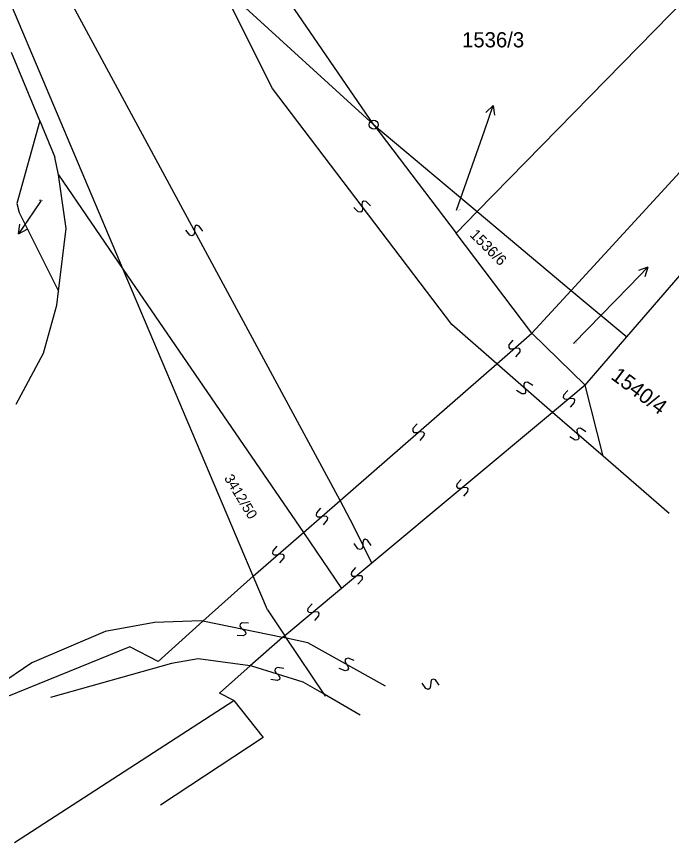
# Model space of a CAD drawing. Extents: x -601196 to -600262, y -1082523 to -1081922.
# Drawn here: x -600445.93 to -600409.27, y -1082422.91 to -1082376.65 of the extents above; entities that cross this region are included whole.
import ezdxf

# ---------------------------------------------------------------- set-up
doc = ezdxf.new("R2010")
doc.units = 0
doc.layers.add('Vrstva 47', color=7, linetype='Continuous')

msp = doc.modelspace()

# ---------------------------------------------------------------- linework, layer by layer
at = {"layer": 'Vrstva 47'}
for p, q in [((-600420.14, -1082387.57), (-600313.5, -1082278.63)), ((-600394.57, -1082369.86), (-600414.88, -1082391.99)), ((-600427.81, -1082403.75), (-600444.13, -1082373.53)), ((-600425.93, -1082382.71), (-600431.86, -1082374.05)), ((-600431.6, -1082380.69), (-600434.49, -1082374.9)), ((-600434.49, -1082374.9), (-600425.93, -1082382.71)), ((-600439.95, -1082390.82), (-600446.47, -1082375.4)), ((-600444.63, -1082382.49), (-600446.21, -1082378.67)), ((-600421.56, -1082393.91), (-600431.6, -1082380.69)), ((-600411.77, -1082394.6), (-600399.71, -1082380.62)), ((-600419.74, -1082383.05), (-600419.251, -1082381.631)), ((-600419.251, -1082381.631), (-600419.65, -1082382.023)), ((-600419.251, -1082381.631), (-600419.178, -1082382.185)), ((-600444.63, -1082382.49), (-600445.91, -1082387.13)), ((-600444.63, -1082382.49), (-600443.79, -1082384.53)), ((-600425.93, -1082382.71), (-600421.32, -1082388.78)), ((-600425.93, -1082382.71), (-600420.14, -1082387.57)), ((-600421.3, -1082387.5), (-600419.74, -1082383.05)), ((-600443.58, -1082385.51), (-600443.79, -1082384.53)), ((-600443.58, -1082385.51), (-600439.95, -1082390.82)), ((-600443.14, -1082388.53), (-600443.58, -1082385.51)), ((-600445.91, -1082387.13), (-600445.77, -1082387.63)), ((-600444.54, -1082386.96), (-600444.97, -1082387.59)), ((-600426.581, -1082387.05), (-600426.6, -1082387.19)), ((-600426.501, -1082386.989), (-600426.581, -1082387.05)), ((-600426.361, -1082387.008), (-600426.501, -1082386.989)), ((-600426.11, -1082387.257), (-600426.361, -1082387.008)), ((-600444.97, -1082387.59), (-600445.817, -1082388.827)), ((-600445.77, -1082387.63), (-600443.57, -1082392.04)), ((-600426.798, -1082387.591), (-600427.049, -1082387.342)), ((-600426.658, -1082387.61), (-600426.798, -1082387.591)), ((-600426.578, -1082387.55), (-600426.658, -1082387.61)), ((-600426.6, -1082387.19), (-600426.559, -1082387.409)), ((-600426.559, -1082387.409), (-600426.578, -1082387.55)), ((-600421.32, -1082388.78), (-600420.14, -1082387.57)), ((-600420.14, -1082387.57), (-600414.88, -1082391.99)), ((-600445.817, -1082388.827), (-600445.741, -1082388.274)), ((-600445.817, -1082388.827), (-600445.328, -1082388.556)), ((-600443.57, -1082392.04), (-600443.14, -1082388.53)), ((-600435.933, -1082388.392), (-600435.973, -1082388.528)), ((-600435.973, -1082388.528), (-600435.966, -1082388.751)), ((-600435.845, -1082388.345), (-600435.933, -1082388.392)), ((-600435.709, -1082388.385), (-600435.845, -1082388.345)), ((-600435.499, -1082388.669), (-600435.709, -1082388.385)), ((-600436.23, -1082388.894), (-600436.44, -1082388.61)), ((-600436.094, -1082388.934), (-600436.23, -1082388.894)), ((-600436.006, -1082388.887), (-600436.094, -1082388.934)), ((-600435.966, -1082388.751), (-600436.006, -1082388.887)), ((-600417.08, -1082394.38), (-600421.32, -1082388.78)), ((-600439.95, -1082390.82), (-600429.87, -1082405.55)), ((-600432.68, -1082408), (-600439.95, -1082390.82)), ((-600411.63, -1082391.77), (-600410.588, -1082390.691)), ((-600410.588, -1082390.691), (-600411.115, -1082390.877)), ((-600410.588, -1082390.691), (-600410.755, -1082391.224)), ((-600414.75, -1082394.96), (-600411.63, -1082391.77)), ((-600443.66, -1082392.81), (-600443.57, -1082392.04)), ((-600417.08, -1082394.38), (-600414.88, -1082391.99)), ((-600414.88, -1082391.99), (-600411.77, -1082394.6)), ((-600444.41, -1082395.51), (-600443.66, -1082392.81)), ((-600419.05, -1082396.1), (-600421.56, -1082393.91)), ((-600419.05, -1082396.1), (-600417.08, -1082394.38)), ((-600417.08, -1082394.38), (-600414.1, -1082397.3)), ((-600418.139, -1082394.774), (-600418.37, -1082395.042)), ((-600414.1, -1082397.3), (-600411.77, -1082394.6)), ((-600418.37, -1082395.042), (-600418.38, -1082395.183)), ((-600418.38, -1082395.183), (-600418.314, -1082395.258)), ((-600418.314, -1082395.258), (-600418.173, -1082395.268)), ((-600418.173, -1082395.268), (-600417.956, -1082395.211)), ((-600417.759, -1082395.437), (-600417.99, -1082395.705)), ((-600417.956, -1082395.211), (-600417.815, -1082395.221)), ((-600417.815, -1082395.221), (-600417.749, -1082395.296)), ((-600417.749, -1082395.296), (-600417.759, -1082395.437)), ((-600445.94, -1082398.37), (-600444.41, -1082395.51)), ((-600427.81, -1082403.75), (-600419.05, -1082396.1)), ((-600415.92, -1082398.82), (-600419.05, -1082396.1)), ((-600417.471, -1082397.14), (-600417.537, -1082397.215)), ((-600417.537, -1082397.215), (-600417.527, -1082397.356)), ((-600417.33, -1082397.13), (-600417.471, -1082397.14)), ((-600417.033, -1082397.322), (-600417.33, -1082397.13)), ((-600414.1, -1082397.3), (-600415.92, -1082398.82)), ((-600413.1, -1082401.27), (-600414.1, -1082397.3)), ((-600417.639, -1082397.789), (-600417.936, -1082397.597)), ((-600417.498, -1082397.779), (-600417.639, -1082397.789)), ((-600417.527, -1082397.356), (-600417.442, -1082397.563)), ((-600417.432, -1082397.704), (-600417.498, -1082397.779)), ((-600417.442, -1082397.563), (-600417.432, -1082397.704)), ((-600415.074, -1082397.592), (-600415.311, -1082397.855)), ((-600415.311, -1082397.855), (-600415.323, -1082397.996)), ((-600415.323, -1082397.996), (-600415.259, -1082398.073)), ((-600415.259, -1082398.073), (-600415.118, -1082398.085)), ((-600415.118, -1082398.085), (-600414.901, -1082398.034)), ((-600414.708, -1082398.264), (-600414.945, -1082398.527)), ((-600414.901, -1082398.034), (-600414.76, -1082398.046)), ((-600414.76, -1082398.046), (-600414.696, -1082398.123)), ((-600414.696, -1082398.123), (-600414.708, -1082398.264)), ((-600415.92, -1082398.82), (-600426.04, -1082407.27)), ((-600413.1, -1082401.27), (-600415.92, -1082398.82)), ((-600423.504, -1082399.459), (-600423.735, -1082399.727)), ((-600423.735, -1082399.727), (-600423.745, -1082399.868)), ((-600423.745, -1082399.868), (-600423.679, -1082399.943)), ((-600423.679, -1082399.943), (-600423.538, -1082399.953)), ((-600423.538, -1082399.953), (-600423.321, -1082399.896)), ((-600423.321, -1082399.896), (-600423.18, -1082399.906)), ((-600423.18, -1082399.906), (-600423.114, -1082399.981)), ((-600423.114, -1082399.981), (-600423.124, -1082400.122)), ((-600414.497, -1082399.725), (-600414.562, -1082399.8)), ((-600414.562, -1082399.8), (-600414.552, -1082399.941)), ((-600414.552, -1082399.941), (-600414.467, -1082400.148)), ((-600414.355, -1082399.715), (-600414.497, -1082399.725)), ((-600414.058, -1082399.907), (-600414.355, -1082399.715)), ((-600423.124, -1082400.122), (-600423.355, -1082400.39)), ((-600414.664, -1082400.374), (-600414.961, -1082400.183)), ((-600414.522, -1082400.364), (-600414.664, -1082400.374)), ((-600414.457, -1082400.289), (-600414.522, -1082400.364)), ((-600414.467, -1082400.148), (-600414.457, -1082400.289)), ((-600409.39, -1082404.49), (-600413.1, -1082401.27)), ((-600421.281, -1082402.84), (-600421.293, -1082402.981)), ((-600421.044, -1082402.577), (-600421.281, -1082402.84)), ((-600421.293, -1082402.981), (-600421.229, -1082403.058)), ((-600421.229, -1082403.058), (-600421.088, -1082403.07)), ((-600421.088, -1082403.07), (-600420.871, -1082403.019)), ((-600420.678, -1082403.249), (-600420.915, -1082403.512)), ((-600420.871, -1082403.019), (-600420.73, -1082403.031)), ((-600420.73, -1082403.031), (-600420.666, -1082403.108)), ((-600420.666, -1082403.108), (-600420.678, -1082403.249)), ((-600429.87, -1082405.55), (-600427.81, -1082403.75)), ((-600427.06, -1082405.17), (-600427.81, -1082403.75)), ((-600428.914, -1082404.184), (-600429.145, -1082404.452)), ((-600429.145, -1082404.452), (-600429.155, -1082404.593)), ((-600429.155, -1082404.593), (-600429.089, -1082404.668)), ((-600429.089, -1082404.668), (-600428.948, -1082404.678)), ((-600428.948, -1082404.678), (-600428.731, -1082404.621)), ((-600428.731, -1082404.621), (-600428.59, -1082404.631)), ((-600428.59, -1082404.631), (-600428.524, -1082404.706)), ((-600428.524, -1082404.706), (-600428.534, -1082404.847)), ((-600428.534, -1082404.847), (-600428.765, -1082405.115)), ((-600426.04, -1082407.27), (-600427.06, -1082405.17)), ((-600432.68, -1082408), (-600429.87, -1082405.55)), ((-600429.87, -1082405.55), (-600427.73, -1082408.68)), ((-600426.548, -1082406.108), (-600426.551, -1082406.331)), ((-600426.502, -1082405.974), (-600426.548, -1082406.108)), ((-600426.412, -1082405.93), (-600426.502, -1082405.974)), ((-600426.278, -1082405.977), (-600426.412, -1082405.93)), ((-600426.08, -1082406.27), (-600426.278, -1082405.977)), ((-600431.58, -1082406.576), (-600431.59, -1082406.718)), ((-600431.349, -1082406.309), (-600431.58, -1082406.576)), ((-600426.821, -1082406.462), (-600427.019, -1082406.169)), ((-600426.687, -1082406.509), (-600426.821, -1082406.462)), ((-600426.597, -1082406.465), (-600426.687, -1082406.509)), ((-600426.551, -1082406.331), (-600426.597, -1082406.465)), ((-600431.59, -1082406.718), (-600431.524, -1082406.793)), ((-600431.524, -1082406.793), (-600431.383, -1082406.803)), ((-600431.383, -1082406.803), (-600431.166, -1082406.746)), ((-600430.969, -1082406.973), (-600431.2, -1082407.24)), ((-600431.166, -1082406.746), (-600431.025, -1082406.756)), ((-600431.025, -1082406.756), (-600430.959, -1082406.832)), ((-600430.959, -1082406.832), (-600430.969, -1082406.973)), ((-600426.04, -1082407.27), (-600427.73, -1082408.68)), ((-600426.949, -1082407.507), (-600427.186, -1082407.77)), ((-600427.186, -1082407.77), (-600427.198, -1082407.911)), ((-600427.198, -1082407.911), (-600427.134, -1082407.987)), ((-600426.993, -1082408), (-600426.776, -1082407.949)), ((-600426.776, -1082407.949), (-600426.635, -1082407.962)), ((-600426.635, -1082407.962), (-600426.571, -1082408.038)), ((-600432.68, -1082408), (-600435.49, -1082410.52)), ((-600431.88, -1082409.88), (-600432.68, -1082408)), ((-600427.134, -1082407.987), (-600426.993, -1082408)), ((-600426.584, -1082408.179), (-600426.82, -1082408.442)), ((-600426.571, -1082408.038), (-600426.584, -1082408.179)), ((-600427.73, -1082408.68), (-600430.91, -1082411.33)), ((-600429.62, -1082409.8), (-600429.633, -1082409.94)), ((-600429.384, -1082409.537), (-600429.62, -1082409.8)), ((-600431.88, -1082409.88), (-600430.91, -1082411.33)), ((-600429.633, -1082409.94), (-600429.569, -1082410.017)), ((-600429.569, -1082410.017), (-600429.428, -1082410.03)), ((-600429.428, -1082410.03), (-600429.211, -1082409.979)), ((-600429.019, -1082410.209), (-600429.255, -1082410.472)), ((-600429.211, -1082409.979), (-600429.07, -1082409.992)), ((-600429.07, -1082409.992), (-600429.006, -1082410.069)), ((-600429.006, -1082410.069), (-600429.019, -1082410.209)), ((-600438.2, -1082410.59), (-600440.96, -1082411.09)), ((-600435.59, -1082410.5), (-600438.2, -1082410.59)), ((-600435.49, -1082410.52), (-600438, -1082412.77)), ((-600435.49, -1082410.52), (-600435.59, -1082410.5)), ((-600431.03, -1082411.43), (-600435.49, -1082410.52)), ((-600433.405, -1082410.69), (-600433.425, -1082410.788)), ((-600433.288, -1082410.612), (-600433.405, -1082410.69)), ((-600432.935, -1082410.633), (-600433.288, -1082410.612)), ((-600440.96, -1082411.09), (-600445.07, -1082412.85)), ((-600433.425, -1082410.788), (-600433.347, -1082410.906)), ((-600433.347, -1082410.906), (-600433.172, -1082411.043)), ((-600433.172, -1082411.043), (-600433.094, -1082411.161)), ((-600433.094, -1082411.161), (-600433.114, -1082411.259)), ((-600433.231, -1082411.337), (-600433.584, -1082411.316)), ((-600433.114, -1082411.259), (-600433.231, -1082411.337)), ((-600431.03, -1082411.43), (-600432.84, -1082413.02)), ((-600430.91, -1082411.33), (-600431.03, -1082411.43)), ((-600430.81, -1082411.47), (-600431.03, -1082411.43)), ((-600430.81, -1082411.47), (-600430.91, -1082411.33)), ((-600429.63, -1082411.72), (-600430.81, -1082411.47)), ((-600428.71, -1082414.61), (-600430.81, -1082411.47)), ((-600439.59, -1082411.96), (-600449.97, -1082416.17)), ((-600438, -1082412.77), (-600439.59, -1082411.96)), ((-600425.27, -1082414.16), (-600429.63, -1082411.72)), ((-600427.366, -1082412.585), (-600427.502, -1082412.624)), ((-600427.036, -1082412.713), (-600427.366, -1082412.585)), ((-600445.07, -1082412.85), (-600449.97, -1082416.17)), ((-600437.25, -1082412.89), (-600444.03, -1082414.79)), ((-600435.76, -1082412.62), (-600437.25, -1082412.89)), ((-600432.84, -1082413.02), (-600435.76, -1082412.62)), ((-600434.57, -1082414.54), (-600432.84, -1082413.02)), ((-600432.76, -1082413.03), (-600432.84, -1082413.02)), ((-600429.89, -1082413.93), (-600432.76, -1082413.03)), ((-600427.502, -1082412.624), (-600427.551, -1082412.711)), ((-600427.551, -1082412.711), (-600427.512, -1082412.847)), ((-600427.512, -1082412.847), (-600427.387, -1082413.032)), ((-600427.387, -1082413.032), (-600427.348, -1082413.168)), ((-600431.441, -1082413.181), (-600431.47, -1082413.277)), ((-600431.47, -1082413.277), (-600431.405, -1082413.402)), ((-600431.315, -1082413.116), (-600431.441, -1082413.181)), ((-600431.405, -1082413.402), (-600431.244, -1082413.557)), ((-600430.966, -1082413.173), (-600431.315, -1082413.116)), ((-600427.533, -1082413.294), (-600427.863, -1082413.166)), ((-600427.397, -1082413.255), (-600427.533, -1082413.294)), ((-600427.348, -1082413.168), (-600427.397, -1082413.255)), ((-600431.334, -1082413.843), (-600431.683, -1082413.786)), ((-600431.208, -1082413.778), (-600431.334, -1082413.843)), ((-600431.244, -1082413.557), (-600431.179, -1082413.682)), ((-600431.179, -1082413.682), (-600431.208, -1082413.778)), ((-600428.71, -1082414.61), (-600429.89, -1082413.93)), ((-600423.016, -1082414.288), (-600423.214, -1082413.995)), ((-600422.743, -1082413.933), (-600422.746, -1082414.156)), ((-600422.697, -1082413.799), (-600422.743, -1082413.933)), ((-600422.607, -1082413.755), (-600422.697, -1082413.799)), ((-600422.473, -1082413.802), (-600422.607, -1082413.755)), ((-600422.275, -1082414.094), (-600422.473, -1082413.802)), ((-600422.882, -1082414.334), (-600423.016, -1082414.288)), ((-600422.792, -1082414.29), (-600422.882, -1082414.334)), ((-600422.746, -1082414.156), (-600422.792, -1082414.29)), ((-600433.76, -1082414.96), (-600434.57, -1082414.54)), ((-600426.69, -1082415.78), (-600428.71, -1082414.61)), ((-600428.63, -1082414.73), (-600428.71, -1082414.61)), ((-600446.04, -1082422.91), (-600433.76, -1082414.96)), ((-600433.76, -1082414.96), (-600432.12, -1082417.03)), ((-600432.12, -1082417.03), (-600437.87, -1082420.82))]:
    msp.add_line(p, q, dxfattribs=at)
for radius in [0.25, 0.005]:
    msp.add_circle((-600425.93, -1082382.71), radius, dxfattribs=at)

# ---------------------------------------------------------------- texts
for s, height, p in [('1536/3', 0.85, (-600420.99, -1082378.38)), ('3585/30', 0.05, (-600444.688, -1082386.96)), ('1536/3', 0.05, (-600421.3, -1082387.5)), ('1539/1', 0.05, (-600414.75, -1082394.96))]:
    msp.add_text(s, height=height, dxfattribs=at).set_placement(p)
for s, height, rotation, p in [('1536/6', 0.6, 315, (-600420.59, -1082388.92)), ('1540/4', 0.85, 323.1, (-600412.71, -1082396.91)), ('3412/50', 0.57, 301.1495, (-600434.326, -1082402.502))]:
    msp.add_text(s, height=height, rotation=rotation, dxfattribs=at).set_placement(p)

doc.saveas('drawing.dxf')
